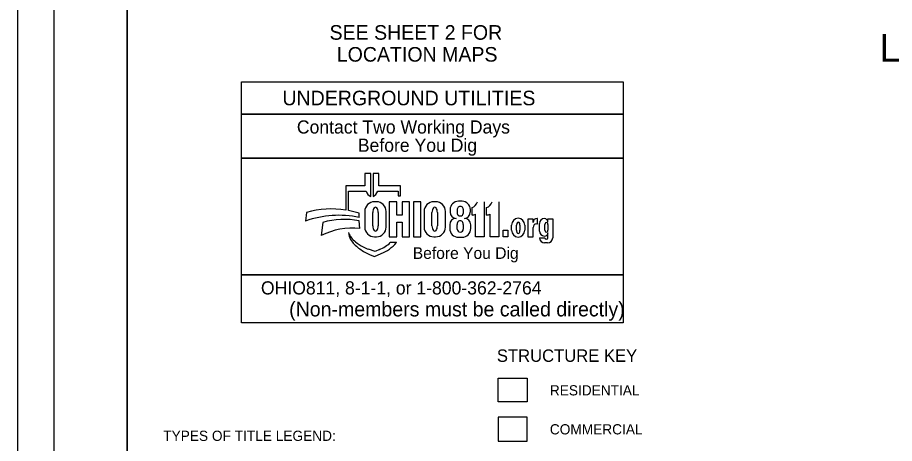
# Model space of a CAD drawing. Extents: x -1 to 48.3, y -9.3 to 22.
# Drawn here: x 0 to 12, y 8.06 to 13.9 of the extents above; entities that cross this region are included whole.
import ezdxf

# ---------------------------------------------------------------- set-up
doc = ezdxf.new("R2010")
doc.units = 0
for name, color, linetype in [('GM_X_Adjacent_County', 7, 'Continuous'), ('GM_X_Adjacent_County_Text', 7, 'Continuous'), ('GM_X_County', 7, 'Continuous'), ('GM_X_Minor_Lake', 7, 'Continuous'), ('GM_X_Township', 7, 'Continuous')]:
    doc.layers.add(name, color=color, linetype=linetype)

msp = doc.modelspace()

# ---------------------------------------------------------------- linework, layer by layer
at = {"layer": 'GM_X_Adjacent_County'}
msp.add_lwpolyline([(6.576, 8.097), (6.973, 8.097), (6.973, 8.423), (6.576, 8.423)], close=True, dxfattribs=at)
at = {"layer": 'GM_X_Adjacent_County_Text'}
msp.add_lwpolyline([(0, 0), (34, 0), (34, 22), (0, 22)], close=True, dxfattribs=at)
at = {"layer": 'GM_X_County'}
for p, q in [((4.834, 11.762), (4.754, 11.762)), ((4.754, 11.762), (4.754, 11.595)), ((4.834, 11.445), (4.834, 11.762)), ((4.945, 11.762), (4.865, 11.762)), ((4.865, 11.762), (4.865, 11.445)), ((4.945, 11.595), (4.945, 11.762)), ((4.754, 11.595), (4.491, 11.595)), ((4.491, 11.595), (4.491, 11.261)), ((5.243, 11.595), (4.945, 11.595)), ((5.243, 11.455), (5.243, 11.595)), ((4.529, 11.254), (4.529, 11.519)), ((4.529, 11.519), (4.77, 11.519)), ((4.93, 11.519), (5.208, 11.519)), ((5.208, 11.519), (5.208, 11.455)), ((5.208, 11.455), (5.243, 11.455)), ((4.911, 11.374), (4.886, 11.374)), ((5.189, 11.373), (5.087, 11.373)), ((5.087, 11.373), (5.087, 10.895)), ((5.722, 11.374), (5.697, 11.374)), ((6.083, 11.381), (6.034, 11.381)), ((6.22, 11.192), (6.22, 11.294)), ((6.386, 11.373), (6.386, 10.895)), ((6.42, 11.192), (6.42, 11.294)), ((6.587, 11.373), (6.587, 10.895)), ((3.956, 11.227), (3.942, 11.11)), ((4.675, 11.159), (4.675, 11.217)), ((4.753, 11.241), (4.753, 11.028)), ((4.861, 11.045), (4.861, 11.228)), ((4.936, 11.228), (4.936, 11.045)), ((5.045, 11.028), (5.045, 11.241)), ((5.563, 11.241), (5.563, 11.028)), ((5.672, 11.045), (5.672, 11.228)), ((5.747, 11.228), (5.747, 11.045)), ((5.855, 11.028), (5.855, 11.241)), ((5.92, 11.267), (5.92, 11.23)), ((6.019, 11.213), (6.019, 11.272)), ((6.1, 11.272), (6.1, 11.213)), ((6.197, 11.23), (6.197, 11.267)), ((6.268, 10.895), (6.268, 11.206)), ((6.468, 10.895), (6.468, 11.206)), ((4.177, 11.092), (4.155, 10.912)), ((4.685, 11.009), (4.676, 11.115)), ((5.189, 10.895), (5.189, 11.097)), ((5.914, 11.06), (5.914, 11.009)), ((6.015, 11.001), (6.015, 11.062)), ((6.1, 11.062), (6.1, 11.001)), ((6.203, 11.009), (6.203, 11.06)), ((6.76, 10.986), (6.76, 11.053)), ((6.828, 10.984), (6.828, 11.053)), ((6.876, 11.053), (6.876, 10.984)), ((6.943, 11.053), (6.943, 10.986)), ((7.055, 11.138), (6.982, 11.138)), ((6.982, 11.138), (6.982, 10.895)), ((7.055, 11.091), (7.055, 11.138)), ((7.105, 11.071), (7.116, 11.071)), ((7.116, 11.146), (7.11, 11.146)), ((7.116, 11.071), (7.116, 11.146)), ((7.144, 10.973), (7.144, 11.077)), ((7.217, 10.987), (7.217, 11.063)), ((7.259, 11.093), (7.259, 11.14)), ((7.259, 11.14), (7.324, 11.14)), ((7.259, 11.063), (7.259, 10.987)), ((7.324, 11.14), (7.324, 10.881)), ((4.528, 10.955), (4.533, 10.928)), ((7.055, 10.895), (7.055, 11.022)), ((7.259, 10.881), (7.259, 10.951)), ((4.886, 10.895), (4.911, 10.895)), ((5.087, 10.895), (5.189, 10.895)), ((5.186, 10.815), (5.101, 10.815)), ((5.184, 10.812), (5.186, 10.815)), ((5.697, 10.895), (5.722, 10.895)), ((6.035, 10.889), (6.082, 10.889)), ((6.386, 10.895), (6.268, 10.895)), ((6.587, 10.895), (6.468, 10.895)), ((6.982, 10.895), (7.055, 10.895)), ((7.144, 10.881), (7.217, 10.881)), ((7.254, 10.811), (7.214, 10.811)), ((4.893, 10.694), (4.804, 10.725)), ((4.954, 10.721), (4.893, 10.694)), ((4.828, 10.648), (4.884, 10.624)), ((4.884, 10.624), (4.978, 10.665)), ((8.29, 9.716), (3.065, 9.716))]:
    msp.add_line(p, q, dxfattribs=at)
for points in [[(3.065, 13.016), (8.29, 13.016), (8.29, 12.576), (3.065, 12.576)], [(3.065, 12.576), (8.29, 12.576), (8.29, 11.971), (3.065, 11.971)], [(3.065, 11.971), (8.29, 11.971), (8.29, 10.376), (3.065, 10.376)], [(6.645, 10.984), (6.71, 10.984), (6.71, 10.895), (6.645, 10.895)], [(3.065, 10.376), (8.29, 10.376), (8.29, 9.716), (3.065, 9.716)]]:
    msp.add_lwpolyline(points, close=True, dxfattribs=at)
for points in [[(5.189, 11.097), (5.265, 11.097), (5.265, 10.895), (5.366, 10.895), (5.366, 11.373), (5.265, 11.373), (5.265, 11.192), (5.189, 11.192), (5.189, 11.373)], [(5.417, 10.895), (5.52, 10.895), (5.52, 11.373), (5.417, 11.373), (5.417, 10.895)], [(6.001, 11.147), (6.001, 11.147)], [(6.116, 11.147), (6.116, 11.147)]]:
    msp.add_lwpolyline(points, dxfattribs=at)
for centre, radius, start, end in [((4.906, 11.573), 0.147, 201.9296, 240.7469), ((4.793, 11.573), 0.147, 299.2531, 338.0704), ((4.886, 11.241), 0.134, 90, 180), ((4.911, 11.241), 0.134, 0, 90), ((5.697, 11.241), 0.134, 90, 180), ((5.722, 11.241), 0.134, 0, 90), ((6.034, 11.267), 0.114, 90, 180), ((6.083, 11.267), 0.114, 0, 90), ((6.169, 11.416), 0.132, 292.5572, 340.7355), ((6.369, 11.416), 0.132, 292.5572, 340.7355), ((4.394, 9.857), 1.332, 77.8238, 109.8274), ((4.3, 10.052), 1.224, 81.0007, 106.3144), ((4.3, 10.052), 1.224, 72.1402, 79.2074), ((6.004, 11.23), 0.0837, 180, 268.1442), ((6.113, 11.23), 0.0837, 272.2058, 0), ((6.208, 11.324), 0.132, 275.1733, 297.0931), ((6.408, 11.324), 0.132, 275.1733, 297.0931), ((4.475, 10.039), 1.094, 79.44, 105.8467), ((6.001, 11.06), 0.0865, 90, 180), ((6.116, 11.06), 0.0865, 0, 90), ((6.856, 11.053), 0.0956, 92.5886, 180), ((6.847, 11.053), 0.0956, 0, 87.4114), ((7.11, 11.091), 0.0548, 90, 180), ((7.105, 11.022), 0.0493, 90, 180), ((7.213, 11.077), 0.0686, 92.6865, 180), ((7.207, 11.093), 0.0524, 0, 86.9262), ((4.583, 10.064), 0.95, 83.8248, 116.8021), ((4.808, 11.063), 0.3, 201.0457, 232.5314), ((4.744, 10.964), 0.214, 189.6817, 216.0884), ((4.886, 11.028), 0.134, 180, 270), ((4.911, 11.028), 0.134, 270, 0), ((5.697, 11.028), 0.134, 180, 270), ((5.722, 11.028), 0.134, 270, 0), ((6.035, 11.009), 0.121, 180, 270), ((6.082, 11.009), 0.121, 270, 0), ((6.856, 10.986), 0.0956, 180, 267.4114), ((6.847, 10.986), 0.0956, 272.5886, 0), ((7.213, 10.973), 0.0692, 180, 265.7132), ((7.213, 10.951), 0.0467, 264.7825, 0), ((4.943, 11.11), 0.461, 216.0884, 235.7167), ((5.095, 11.438), 0.773, 232.5314, 241.794), ((4.74, 11.214), 0.538, 293.4582, 312.0712), ((4.74, 11.214), 0.599, 293.4582, 317.8286), ((7.214, 10.881), 0.0699, 180, 270), ((7.254, 10.881), 0.0699, 270, 0), ((5.192, 11.475), 0.903, 235.7167, 246.2325), ((4.968, 11.201), 0.504, 241.794, 250.9821)]:
    msp.add_arc(centre, radius, start, end, dxfattribs=at)
for centre, major_axis, ratio, start_param, end_param in [((4.899, 11.228), (0, 0.0723), 0.514403, 4.712389, 7.853982), ((5.709, 11.228), (0, 0.0723), 0.514403, 4.712389, 7.853982), ((6.059, 11.272), (0.0404, 0), 0.969373, 0, 3.141593), ((6.059, 11.213), (0.0404, 0), 0.818453, 3.141593, 6.283185), ((4.899, 11.045), (0, 0.0723), 0.514403, 1.570796, 4.712389), ((5.709, 11.045), (0, 0.0723), 0.514403, 1.570796, 4.712389), ((6.058, 11.062), (0, 0.0535), 0.794529, 4.712389, 7.853982), ((6.852, 11.053), (0, 0.0434), 0.553236, 4.712389, 7.853982), ((7.238, 11.063), (0, 0.0275), 0.777179, 4.712389, 7.853982), ((6.058, 11.001), (0.0425, 0), 0.959837, 3.141593, 6.283185), ((6.852, 10.984), (0, 0.046), 0.522014, 1.570796, 4.712389), ((7.238, 10.987), (0, 0.0275), 0.777179, 1.570796, 4.712389), ((7.238, 10.881), (0.0214, 0), 0.959012, 3.141593, 6.283185)]:
    msp.add_ellipse(centre, major_axis=major_axis, ratio=ratio, start_param=start_param, end_param=end_param, dxfattribs=at)
at = {"layer": 'GM_X_Minor_Lake'}
for points in [[(0.5, 21.5), (1.5, 21.5), (1.5, 0.5), (0.5, 0.5)], [(1.5, 21.5), (33.5, 21.5), (33.5, 0.5), (1.5, 0.5)]]:
    msp.add_lwpolyline(points, close=True, dxfattribs=at)
at = {"layer": 'GM_X_Township'}
msp.add_lwpolyline([(6.576, 8.959), (6.973, 8.959), (6.973, 8.633), (6.576, 8.633)], close=True, dxfattribs=at)

# ---------------------------------------------------------------- texts
at = {"layer": 'GM_X_County'}
for s, height, p in [('SEE SHEET 2 FOR', 0.2, (4.27, 13.594)), ('LOTS 1,4,8,10,11,56,57,66,67, OL 3', 0.38, (11.798, 13.293)), ('LOCATION MAPS', 0.2, (4.369, 13.294)), ('UNDERGROUND UTILITIES', 0.2, (3.625, 12.696)), ('Contact Two Working Days', 0.18, (3.823, 12.309)), ('Before You Dig', 0.18, (4.657, 12.059)), ('Before You Dig', 0.15972, (5.409, 10.592)), ('OHIO811, 8-1-1, or 1-800-362-2764', 0.18, (3.331, 10.105)), ('(Non-members must be called directly)', 0.2, (3.717, 9.804))]:
    msp.add_text(s, height=height, dxfattribs=at).set_placement(p)
at = {"layer": 'GM_X_Township'}
for s, height, p in [('STRUCTURE KEY', 0.17, (6.56, 9.182)), ('RESIDENTIAL', 0.14, (7.285, 8.722)), ('COMMERCIAL', 0.14, (7.285, 8.188)), ('TYPES OF TITLE LEGEND:', 0.14, (1.994, 8.099))]:
    msp.add_text(s, height=height, dxfattribs=at).set_placement(p)

doc.saveas('drawing.dxf')
